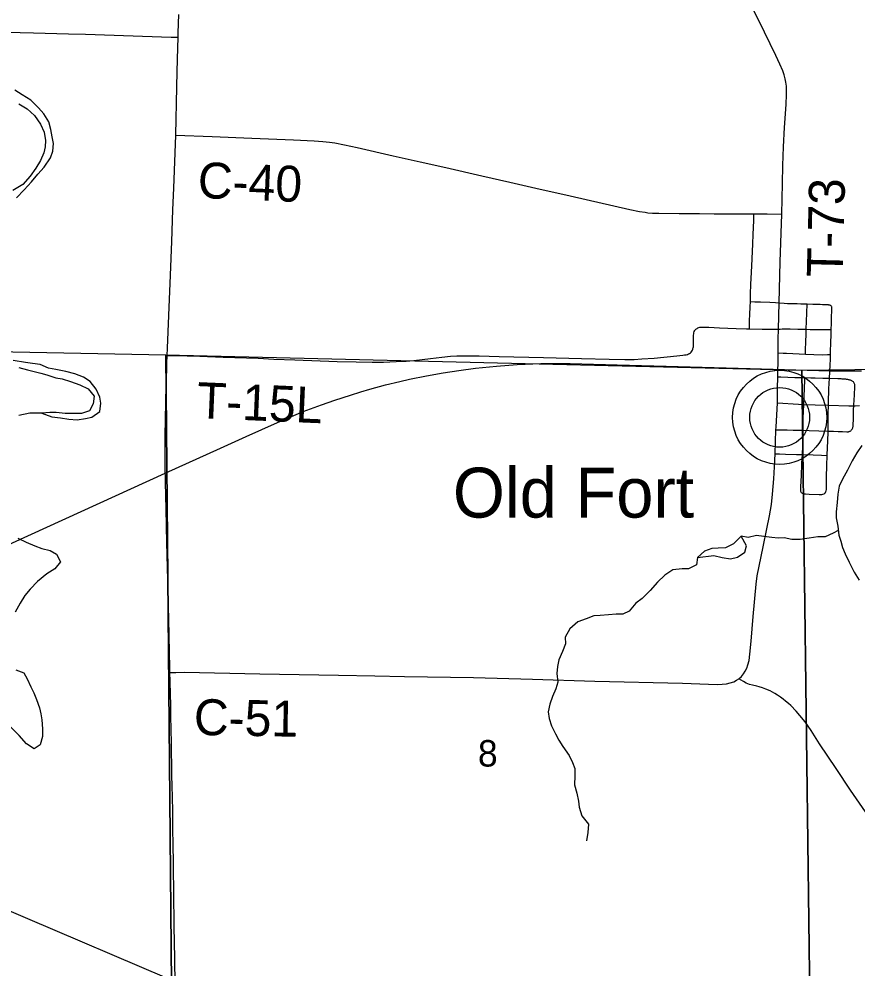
# Model space of a CAD drawing. Extents: x 0 to 34, y 0 to 22.
# Drawn here: x 4.194 to 4.856, y 19.773 to 20.524 of the extents above; entities that cross this region are included whole.
import ezdxf

# ---------------------------------------------------------------- set-up
doc = ezdxf.new("R2010")
doc.units = 0
for name, color, linetype in [('GM_X_Corporation', 7, 'Continuous'), ('GM_X_County_Road', 7, 'Continuous'), ('GM_X_County_Road_Text', 7, 'Continuous'), ('GM_X_Major_River', 7, 'Continuous'), ('GM_X_Minor_Lake', 7, 'Continuous'), ('GM_X_Minor_River', 7, 'Continuous'), ('GM_X_Rail_Line', 7, 'Continuous'), ('GM_X_Section_Text', 7, 'Continuous'), ('GM_X_State_Route', 7, 'Continuous'), ('GM_X_Township_Road', 7, 'Continuous'), ('GM_X_Township_Road_Text', 7, 'Continuous'), ('GM_X_Unincorporated', 7, 'Continuous'), ('GM_X_Unincorporated_Location', 7, 'Continuous'), ('GM_X_Unincorporated_Text', 7, 'Continuous'), ('SH_Text', 7, 'Continuous')]:
    doc.layers.add(name, color=color, linetype=linetype)

msp = doc.modelspace()

# ---------------------------------------------------------------- linework, layer by layer
at = {"layer": 'GM_X_Corporation'}
for points in [[(3.81161, 20.26779), (4.3097, 20.25796), (4.31408, 19.76015), (3.81367, 19.76242)], [(4.81232, 20.24601), (4.81859, 19.74837), (4.31408, 19.76015), (4.3097, 20.25796)], [(5.27452, 20.2518), (5.28249, 19.77411), (5.2855, 19.76944), (5.28927, 19.76403), (5.29858, 19.75162), (5.30572, 19.74448), (5.30919, 19.73639), (4.81859, 19.74837), (4.81232, 20.24601)]]:
    msp.add_lwpolyline(points, close=True, dxfattribs=at)
at = {"layer": 'GM_X_County_Road'}
msp.add_line((4.79115, 20.1799), (4.79189, 20.1989), dxfattribs=at)
for points in [[(3.81205, 20.51692), (3.82841, 20.51693), (3.8508, 20.51679), (3.86074, 20.5167), (3.88032, 20.51657), (3.91047, 20.5163), (3.93378, 20.51615), (3.94466, 20.51608), (3.97418, 20.51587), (4.0121, 20.51563), (4.04411, 20.51538), (4.07085, 20.51521), (4.09229, 20.51483), (4.11777, 20.51451), (4.133, 20.51424), (4.16066, 20.51378), (4.17433, 20.51328), (4.18396, 20.51308), (4.20509, 20.51273), (4.23273, 20.51182), (4.2461, 20.51149), (4.31383, 20.5093), (4.31925, 20.50913)], [(4.31743, 20.43176), (4.34635, 20.43061), (4.3775, 20.42937), (4.41042, 20.42804), (4.42688, 20.42726), (4.4337, 20.42676), (4.43895, 20.42618), (4.44326, 20.42556), (4.4509, 20.42413), (4.46092, 20.42196), (4.48941, 20.41545), (4.51062, 20.41059), (4.53095, 20.40605), (4.55944, 20.39955), (4.58156, 20.39452), (4.60217, 20.38981), (4.62917, 20.38379), (4.67647, 20.37307), (4.68407, 20.37146), (4.68836, 20.37074), (4.69052, 20.37047), (4.69424, 20.37015), (4.6992, 20.36998), (4.71537, 20.36983), (4.73154, 20.3698), (4.74303, 20.36966), (4.76479, 20.36957), (4.77449, 20.36953)], [(4.77449, 20.36953), (4.78484, 20.36951), (4.79653, 20.36938)], [(4.79189, 20.1989), (4.79196, 20.20077), (4.79303, 20.22003)], [(4.79303, 20.22003), (4.80964, 20.21895), (4.81387, 20.2188)], [(4.81387, 20.2188), (4.82282, 20.21848), (4.83335, 20.21818)], [(4.83335, 20.21818), (4.84955, 20.21772), (4.85336, 20.21775)], [(4.85336, 20.21775), (4.85455, 20.21777), (4.85801, 20.21791)], [(4.76252, 20.00195), (4.76455, 20.00378), (4.76629, 20.00588), (4.7676, 20.00792), (4.76881, 20.01038), (4.76975, 20.01296), (4.77062, 20.01654), (4.77134, 20.02143), (4.77233, 20.03162), (4.77395, 20.05114), (4.77627, 20.07685), (4.77712, 20.08334), (4.77852, 20.091), (4.78171, 20.10621), (4.78472, 20.12051), (4.78675, 20.13087), (4.78821, 20.13974), (4.78924, 20.14804), (4.79017, 20.16011), (4.79074, 20.1694), (4.79115, 20.1799)], [(4.31288, 20.00693), (4.31744, 20.00698), (4.3243, 20.00707), (4.38398, 20.00582), (4.44614, 20.00478), (4.47474, 20.00427), (4.49836, 20.00387), (4.55276, 20.00292), (4.59936, 20.00155), (4.64875, 20.00019), (4.71805, 19.9984), (4.7454, 19.99754), (4.74942, 19.99763), (4.75276, 19.99799), (4.75574, 19.99864), (4.75862, 19.99966), (4.76077, 20.00078), (4.76252, 20.00195)], [(4.87225, 19.88304), (4.85087, 19.91382), (4.83934, 19.93094), (4.82639, 19.95065), (4.81969, 19.9611), (4.81486, 19.96793), (4.81086, 19.97304), (4.80775, 19.97647), (4.8036, 19.98078), (4.8017, 19.9825), (4.79948, 19.98431), (4.79743, 19.98596), (4.79537, 19.98752), (4.79315, 19.989), (4.79101, 19.99031), (4.78723, 19.99245), (4.78396, 19.99382), (4.7813, 19.99483), (4.77859, 19.99557), (4.77663, 19.99608), (4.77341, 19.9968), (4.77086, 19.99754), (4.76838, 19.9985), (4.76613, 19.99983), (4.76252, 20.00195)]]:
    msp.add_lwpolyline(points, dxfattribs=at)
at = {"layer": 'GM_X_Major_River'}
msp.add_lwpolyline([(4.85986, 20.18649), (4.85584, 20.18062), (4.85221, 20.17419), (4.84837, 20.167), (4.84435, 20.15981), (4.84185, 20.15413), (4.84068, 20.14787), (4.84026, 20.14123), (4.83946, 20.13402), (4.83942, 20.12908), (4.84071, 20.12262), (4.84161, 20.11559), (4.8431, 20.11083), (4.84458, 20.1057), (4.84645, 20.10075), (4.84962, 20.09428), (4.85374, 20.08628), (4.85768, 20.0798)], dxfattribs=at)
at = {"layer": 'GM_X_Minor_Lake'}
for points in [[(4.72994, 20.09783), (4.74264, 20.09947), (4.74926, 20.09772), (4.75588, 20.09692), (4.76157, 20.09822), (4.76728, 20.10198), (4.76845, 20.1071), (4.76433, 20.11472)], [(4.76433, 20.11472), (4.75842, 20.10868), (4.75196, 20.10549), (4.74609, 20.10514), (4.74116, 20.10498), (4.73527, 20.10274), (4.72994, 20.09783)]]:
    msp.add_lwpolyline(points, dxfattribs=at)
at = {"layer": 'GM_X_Minor_River'}
for points in [[(4.19151, 20.38217), (4.19761, 20.3884), (4.20352, 20.39482), (4.20848, 20.40087), (4.21344, 20.40634), (4.21841, 20.41372), (4.22034, 20.41902), (4.22076, 20.42509), (4.21984, 20.43041), (4.21874, 20.43631), (4.21708, 20.44239), (4.21314, 20.44849), (4.209, 20.45326), (4.20279, 20.45937), (4.19599, 20.46359), (4.19015, 20.46723)], [(4.1933, 20.45658), (4.1999, 20.45256), (4.20593, 20.4472), (4.21062, 20.44053), (4.21343, 20.43406), (4.21452, 20.42741), (4.2143, 20.42247), (4.21314, 20.41773), (4.21045, 20.41167), (4.20681, 20.40562), (4.20241, 20.39938), (4.1965, 20.39277), (4.18871, 20.38807)], [(4.21148, 20.21195), (4.2196, 20.20905), (4.22623, 20.20825), (4.23285, 20.20727), (4.23948, 20.20666), (4.24611, 20.20776), (4.25123, 20.20887), (4.25732, 20.2132), (4.25831, 20.21984), (4.25758, 20.22459), (4.25459, 20.23087), (4.2497, 20.23697), (4.24442, 20.24042), (4.23781, 20.24312), (4.23062, 20.24487), (4.22268, 20.24643), (4.21681, 20.24761), (4.21039, 20.25049), (4.20414, 20.2511), (4.19866, 20.25189), (4.18882, 20.25347)], [(4.19352, 20.24794), (4.20032, 20.24619), (4.20562, 20.24502), (4.21073, 20.24347), (4.21564, 20.2423), (4.22264, 20.23998), (4.22775, 20.239), (4.23417, 20.23688), (4.24154, 20.23436), (4.24815, 20.2311), (4.25285, 20.22537), (4.25206, 20.2193), (4.24918, 20.21381), (4.24292, 20.21157), (4.23004, 20.21165), (4.22303, 20.21245), (4.21792, 20.21248), (4.21148, 20.21195)], [(4.21148, 20.21195), (4.20201, 20.212), (4.19347, 20.21016)], [(4.84113, 20.11932), (4.83708, 20.11714), (4.83081, 20.11432), (4.82494, 20.11417), (4.81811, 20.11307), (4.81091, 20.11216), (4.80428, 20.1122), (4.79841, 20.11338), (4.79368, 20.11302), (4.78857, 20.11362), (4.78232, 20.11442), (4.77645, 20.11521), (4.77, 20.11354), (4.76433, 20.11472), (4.75842, 20.10868), (4.75196, 20.10549), (4.74609, 20.10514), (4.74116, 20.10498), (4.73527, 20.10274), (4.72994, 20.09783), (4.72896, 20.09195), (4.72269, 20.08876), (4.71776, 20.08898), (4.71037, 20.08807), (4.70409, 20.08394), (4.69819, 20.07827), (4.69246, 20.07185), (4.68618, 20.06544), (4.68123, 20.06186), (4.67588, 20.05543), (4.67095, 20.053), (4.66545, 20.05303), (4.65958, 20.05249), (4.65294, 20.05196), (4.64802, 20.05161), (4.64175, 20.04937), (4.6353, 20.04694), (4.62882, 20.04147), (4.62537, 20.03485), (4.62553, 20.02953), (4.62322, 20.02347), (4.62034, 20.01684), (4.61917, 20.01172), (4.61875, 20.00622), (4.61947, 19.99919), (4.61792, 19.99407), (4.61523, 19.98783), (4.61311, 19.98195), (4.61194, 19.97589), (4.61266, 19.97057), (4.61452, 19.96467), (4.61751, 19.95839), (4.62013, 19.95343), (4.62332, 19.94848), (4.62839, 19.94124), (4.63101, 19.93591), (4.63287, 19.93096), (4.63284, 19.92526), (4.6326, 19.91805), (4.63445, 19.91158), (4.63574, 19.90512), (4.63628, 19.90037), (4.63851, 19.89372), (4.64377, 19.88704), (4.64316, 19.8804), (4.64217, 19.87376)], [(4.19268, 20.11315), (4.19929, 20.11007), (4.20609, 20.107), (4.21157, 20.10487), (4.21819, 20.10351), (4.22328, 20.10044), (4.22628, 20.09454), (4.22189, 20.08887), (4.21561, 20.08492), (4.20819, 20.07889), (4.20247, 20.07284), (4.19827, 20.06774), (4.19444, 20.06169), (4.19061, 20.05469)], [(4.19108, 20.00893), (4.19751, 20.00662), (4.20013, 20.00186), (4.20293, 19.99557), (4.20537, 19.99081), (4.20742, 19.98568), (4.20965, 19.97902), (4.21075, 19.97427), (4.21148, 19.96952), (4.21201, 19.9623), (4.21216, 19.95641), (4.21041, 19.94978), (4.20547, 19.94658), (4.19943, 19.95041), (4.19379, 19.95709), (4.18701, 19.96377)]]:
    msp.add_lwpolyline(points, dxfattribs=at)
at = {"layer": 'GM_X_Rail_Line'}
msp.add_lwpolyline([(4.14887, 20.0916), (4.30922, 20.16462), (4.35294, 20.18435), (4.3731, 20.19346), (4.39796, 20.20463), (4.41827, 20.21315), (4.43265, 20.21862), (4.4431, 20.2223), (4.45549, 20.22631), (4.46386, 20.22884), (4.47098, 20.23098), (4.48318, 20.23427), (4.49446, 20.23702), (4.50219, 20.23874), (4.51554, 20.24154), (4.52885, 20.24387), (4.54113, 20.24578), (4.55432, 20.24746), (4.57089, 20.24911), (4.58729, 20.25041), (4.60608, 20.25125), (4.6291, 20.25129), (4.66628, 20.25022), (4.70518, 20.24911), (4.77158, 20.24716), (4.83461, 20.24532), (4.85948, 20.24544)], dxfattribs=at)
at = {"layer": 'GM_X_State_Route'}
for points in [[(4.31304, 19.99986), (4.31288, 20.00693), (4.31277, 20.01214), (4.31258, 20.02176), (4.31226, 20.0376), (4.31199, 20.04815), (4.31167, 20.06026), (4.31138, 20.06957), (4.31108, 20.08044), (4.31084, 20.08976), (4.3104, 20.10961), (4.31014, 20.12228), (4.30981, 20.13654), (4.30951, 20.14615), (4.30911, 20.16943), (4.30903, 20.17564), (4.30899, 20.18496), (4.30909, 20.19396), (4.30925, 20.20731), (4.30955, 20.22005), (4.3099, 20.23402), (4.31008, 20.24054), (4.31031, 20.24644), (4.31047, 20.2511), (4.31071, 20.25766), (4.31089, 20.26322), (4.31195, 20.2893), (4.31322, 20.32098), (4.31425, 20.34769), (4.31524, 20.37276), (4.31593, 20.38993), (4.31697, 20.41789), (4.31743, 20.43176), (4.31785, 20.44461), (4.31815, 20.45673), (4.3184, 20.4701), (4.31854, 20.48159), (4.31887, 20.49184), (4.31925, 20.50913), (4.31933, 20.51266), (4.31978, 20.52726)], [(4.31708, 19.76467), (4.31683, 19.77616), (4.31673, 19.78082), (4.3163, 19.8063), (4.31617, 19.81406), (4.31604, 19.82556), (4.31592, 19.83518), (4.31569, 19.8504), (4.31558, 19.85848), (4.31546, 19.86872), (4.31518, 19.88518), (4.31502, 19.89699), (4.31482, 19.90876), (4.31463, 19.91713), (4.31448, 19.92583), (4.31432, 19.93451), (4.31415, 19.9435), (4.31397, 19.95126), (4.31363, 19.97238), (4.31344, 19.98107), (4.31325, 19.98977), (4.31304, 19.99986)]]:
    msp.add_lwpolyline(points, dxfattribs=at)
at = {"layer": 'GM_X_Township_Road'}
msp.add_line((4.79377, 20.27838), (4.79436, 20.29922), dxfattribs=at)
for points in [[(4.79653, 20.36938), (4.79701, 20.39366), (4.79738, 20.40765), (4.79795, 20.42256), (4.7987, 20.43778), (4.79994, 20.45608), (4.80025, 20.46382), (4.80025, 20.46784), (4.80011, 20.47061), (4.79975, 20.47366), (4.79923, 20.47637), (4.79845, 20.47934), (4.79733, 20.48254), (4.79505, 20.48795), (4.79186, 20.49468), (4.78279, 20.51309), (4.77054, 20.53824)], [(4.77166, 20.30015), (4.77184, 20.30598), (4.77209, 20.3139), (4.7725, 20.32329), (4.77296, 20.33395), (4.77352, 20.34596), (4.77391, 20.35334), (4.77435, 20.36421), (4.77445, 20.36781), (4.77449, 20.36953)], [(4.79436, 20.29922), (4.79529, 20.33167), (4.79653, 20.36938)], [(4.77085, 20.27858), (4.77103, 20.28516), (4.77122, 20.28984), (4.77147, 20.29592), (4.77166, 20.30015)], [(4.77166, 20.30015), (4.77528, 20.30004), (4.7796, 20.2999), (4.78701, 20.29963), (4.79147, 20.29946), (4.79436, 20.29922)], [(4.79436, 20.29922), (4.79825, 20.2989), (4.80098, 20.29877), (4.80526, 20.29865), (4.80869, 20.29855), (4.81146, 20.29847), (4.81445, 20.29839), (4.81647, 20.29833)], [(4.81584, 20.27828), (4.81625, 20.29097), (4.81647, 20.29833)], [(4.81647, 20.29833), (4.82104, 20.2982), (4.8229, 20.29814), (4.82506, 20.29807), (4.82681, 20.29801), (4.8286, 20.29795), (4.82986, 20.29791), (4.83099, 20.29788), (4.83159, 20.29785), (4.83225, 20.29781), (4.83271, 20.29779), (4.83315, 20.29775), (4.8335, 20.29773), (4.8339, 20.29768), (4.83436, 20.29756), (4.83473, 20.29741), (4.83521, 20.29703)], [(4.83554, 20.2781), (4.83565, 20.2829), (4.83577, 20.28838), (4.83591, 20.29247), (4.83598, 20.29548), (4.83591, 20.29598), (4.83572, 20.29638), (4.8355, 20.29671), (4.83521, 20.29703)], [(4.31071, 20.25766), (4.31289, 20.25762), (4.32658, 20.25738), (4.33652, 20.25694), (4.35484, 20.25622), (4.3825, 20.25533), (4.39492, 20.25474), (4.41169, 20.25404), (4.44494, 20.25288), (4.46016, 20.25244), (4.4726, 20.25236), (4.48161, 20.25241), (4.49156, 20.25269), (4.49963, 20.25316), (4.50551, 20.25364), (4.51878, 20.25526), (4.52774, 20.25631), (4.53455, 20.25692), (4.53954, 20.25722), (4.54822, 20.25736), (4.55723, 20.25723), (4.57308, 20.25683), (4.6082, 20.25588), (4.63804, 20.25513), (4.6601, 20.2546), (4.67254, 20.2544), (4.67969, 20.25451), (4.6859, 20.25479), (4.6955, 20.25556), (4.71342, 20.25736), (4.71601, 20.25758), (4.71814, 20.2578), (4.71946, 20.25796), (4.7208, 20.25818), (4.72186, 20.2584), (4.72284, 20.25877), (4.72349, 20.25908), (4.72424, 20.25963), (4.72492, 20.26027), (4.72547, 20.26101), (4.7259, 20.26184), (4.72612, 20.2624), (4.72629, 20.26302), (4.72643, 20.26366), (4.72656, 20.2645), (4.72668, 20.26559), (4.72676, 20.26672), (4.72675, 20.2717), (4.72677, 20.2726), (4.7268, 20.27367), (4.7269, 20.27464), (4.72702, 20.27555), (4.72727, 20.27651), (4.72765, 20.27736), (4.72809, 20.27795), (4.72849, 20.27836), (4.72896, 20.2787), (4.72946, 20.27902), (4.73015, 20.27939), (4.73093, 20.27968), (4.73165, 20.27986), (4.73262, 20.27999), (4.73416, 20.28002), (4.73553, 20.27999), (4.73889, 20.27985), (4.74727, 20.27952), (4.76031, 20.27891), (4.7687, 20.27865), (4.77085, 20.27858)], [(4.77085, 20.27858), (4.781, 20.27825), (4.7924, 20.27837), (4.79377, 20.27838)], [(4.79356, 20.25966), (4.79355, 20.27039), (4.79377, 20.27838)], [(4.79377, 20.27838), (4.7951, 20.27848), (4.79684, 20.27859), (4.79876, 20.27867), (4.80037, 20.2787), (4.80174, 20.27871), (4.80322, 20.27867), (4.80919, 20.27849), (4.81584, 20.27828)], [(4.81518, 20.25861), (4.81527, 20.26125), (4.81553, 20.26911), (4.81568, 20.27371), (4.81584, 20.27828)], [(4.81584, 20.27828), (4.81883, 20.27821), (4.82333, 20.27818), (4.827, 20.27815), (4.83135, 20.27812), (4.83381, 20.27811), (4.83554, 20.2781)], [(4.835, 20.25827), (4.83504, 20.26001), (4.8353, 20.26846), (4.83546, 20.27343), (4.83554, 20.2781)], [(4.79333, 20.24066), (4.79356, 20.2567), (4.79356, 20.25966)], [(4.79356, 20.25966), (4.7976, 20.25942), (4.80009, 20.25928), (4.81518, 20.25861)], [(4.81518, 20.25861), (4.82185, 20.25831), (4.8287, 20.25813), (4.83273, 20.25822), (4.835, 20.25827)], [(4.83415, 20.23957), (4.83474, 20.24983), (4.83491, 20.25478), (4.835, 20.25827)], [(4.79303, 20.22003), (4.7932, 20.23158), (4.79333, 20.24066)], [(4.79333, 20.24066), (4.79565, 20.24059), (4.80684, 20.24023), (4.81088, 20.24014), (4.81475, 20.24006)], [(4.81387, 20.2188), (4.81465, 20.23813), (4.81475, 20.24006)], [(4.81475, 20.24006), (4.81942, 20.23996), (4.82294, 20.23984), (4.82894, 20.23973), (4.83415, 20.23957)], [(4.83335, 20.21818), (4.8334, 20.22026), (4.83373, 20.23112), (4.83415, 20.23957)], [(4.83415, 20.23957), (4.84089, 20.23936), (4.84318, 20.23924), (4.84398, 20.2392), (4.84475, 20.23915), (4.846, 20.23907), (4.84678, 20.239), (4.84748, 20.23893), (4.84838, 20.2388), (4.84903, 20.23866), (4.8495, 20.23856), (4.84998, 20.23842), (4.85042, 20.23825), (4.85107, 20.238), (4.85151, 20.23778), (4.85195, 20.23754), (4.85236, 20.23727), (4.85277, 20.23695), (4.8532, 20.23655)], [(4.85336, 20.21775), (4.85353, 20.2193), (4.85371, 20.22137), (4.854, 20.22722), (4.85424, 20.23194), (4.85426, 20.23294), (4.85425, 20.2334), (4.85423, 20.23388), (4.85412, 20.2346), (4.85397, 20.23524), (4.85375, 20.23579), (4.8535, 20.23618), (4.8532, 20.23655)], [(4.81336, 20.19841), (4.81343, 20.20804), (4.81387, 20.2188)], [(4.83308, 20.19776), (4.83316, 20.20614), (4.83321, 20.21177), (4.83335, 20.21818)], [(4.85136, 20.19846), (4.85162, 20.1987), (4.85188, 20.199), (4.85214, 20.19944), (4.85233, 20.19982), (4.85257, 20.20037), (4.85271, 20.20083), (4.85283, 20.20137), (4.85289, 20.20191), (4.85294, 20.2025), (4.85298, 20.20346), (4.85304, 20.20645), (4.85307, 20.21489), (4.85336, 20.21775)], [(4.79189, 20.1989), (4.79547, 20.19882), (4.80059, 20.19872), (4.80548, 20.19862), (4.81336, 20.19841)], [(4.81271, 20.17916), (4.813, 20.18589), (4.81306, 20.18689), (4.81305, 20.1874), (4.81308, 20.18799), (4.81308, 20.18888), (4.81317, 20.18987), (4.81316, 20.19026), (4.81318, 20.19116), (4.81336, 20.19841)], [(4.81336, 20.19841), (4.818, 20.19826), (4.82586, 20.198), (4.83308, 20.19776)], [(4.83308, 20.19776), (4.83741, 20.1976), (4.84113, 20.19748), (4.84437, 20.19738), (4.84796, 20.19727), (4.84861, 20.19727), (4.8491, 20.19732), (4.84952, 20.19739), (4.84985, 20.19747), (4.85019, 20.19761), (4.85056, 20.19781), (4.85099, 20.19811), (4.85136, 20.19846)], [(4.83224, 20.17861), (4.83255, 20.18505), (4.83276, 20.18949), (4.83308, 20.19776)], [(4.79115, 20.1799), (4.79456, 20.17979), (4.79938, 20.17962), (4.8081, 20.1793), (4.81271, 20.17916)], [(4.83066, 20.14876), (4.8302, 20.14833), (4.82957, 20.14788), (4.82874, 20.14759), (4.82792, 20.1474), (4.82704, 20.14735), (4.8261, 20.14729), (4.81823, 20.14766), (4.81512, 20.14788), (4.81446, 20.14793), (4.81387, 20.14806), (4.81337, 20.14822), (4.81294, 20.14841), (4.81247, 20.1487), (4.81207, 20.14907), (4.81178, 20.14949), (4.81159, 20.15003), (4.81151, 20.15053), (4.81146, 20.15204), (4.81156, 20.15412), (4.8118, 20.15757), (4.81207, 20.16309), (4.81217, 20.16585), (4.81228, 20.16838), (4.81244, 20.17242), (4.81258, 20.17578), (4.81271, 20.17916)], [(4.81271, 20.17916), (4.82139, 20.17891), (4.82773, 20.17872), (4.83224, 20.17861)], [(4.83066, 20.14876), (4.83105, 20.14931), (4.83137, 20.14995), (4.83159, 20.15064), (4.83169, 20.15152), (4.83172, 20.15282), (4.83172, 20.15481), (4.83175, 20.16148), (4.83199, 20.1707), (4.83224, 20.17861)]]:
    msp.add_lwpolyline(points, dxfattribs=at)
at = {"layer": 'GM_X_Unincorporated'}
for radius in [0.0372, 0.02358]:
    msp.add_circle((4.7948, 20.20866), radius, dxfattribs=at)
at = {"layer": 'GM_X_Unincorporated_Location'}
msp.add_line((4.7948, 20.20866), (4.7948, 20.20866), dxfattribs=at)
at = {"layer": 'SH_Text'}
msp.add_lwpolyline([(9.29702, 16.88204), (2.59655, 20.49713), (9.29702, 17.63625)], close=True, dxfattribs=at)

# ---------------------------------------------------------------- texts
at = {"layer": 'GM_X_County_Road_Text'}
for s, rotation, p in [('C-40', 357.59979, (4.33445, 20.38219)), ('C-51', 358.97596, (4.33162, 19.95758))]:
    msp.add_text(s, height=0.028409, rotation=rotation, dxfattribs=at).set_placement(p)
at = {"layer": 'GM_X_Section_Text'}
msp.add_text('8', height=0.02093, rotation=0.00001, dxfattribs=at).set_placement((4.55631, 19.93258))
at = {"layer": 'GM_X_Township_Road_Text'}
for s, rotation, p in [('T-73', 88.57607, (4.84458, 20.31924)), ('T-15L', 357.57251, (4.33371, 20.20814))]:
    msp.add_text(s, height=0.028409, rotation=rotation, dxfattribs=at).set_placement(p)
at = {"layer": 'GM_X_Unincorporated_Text'}
msp.add_text('Old Fort', height=0.039489, rotation=0.00001, dxfattribs=at).set_placement((4.53652, 20.1294))

doc.saveas('drawing.dxf')
